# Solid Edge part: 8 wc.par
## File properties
Author: Henri
Template: Normal.par
Last saved by: Henri
Revision: 2
Application: Solid Edge
Accuracy: 0,990
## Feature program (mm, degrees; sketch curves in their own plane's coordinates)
sketch for "unnamed Protrusion 1" plane through (0, 0, 0) normal (0, 0, 1) x-axis (1, 0, 0)
  line (35, -25) -> (-35, -25)
  line (-35, -25) -> (-35, 25)
  line (-35, 25) -> (35, 25)
  line (35, 25) -> (35, -25)
extrude "unnamed Protrusion 1" add finite 2.5 along +normal
sketch for "ExtrudedProtrusion_3" plane through (0, 0, 2.5) normal (0, 0, 1) x-axis (0, 1, 0)
  line (7, 25) -> (7.9468, 13.7663)
  line (7, 30) -> (7, 25)
  line (7, 30) -> (-7, 30)
  line (-7, 30) -> (-7, 25)
  line (-7, 25) -> (-7.9468, 13.7663)
extrude "ExtrudedProtrusion_3" add finite 2.5 along +normal
lofted protrusion "unnamed LoftedProtrusion 1"
lofted protrusion "unnamed LoftedProtrusion 2"
lofted cutout "unnamed LoftedCutout 1"
lofted protrusion "unnamed LoftedProtrusion 3"
lofted cutout "unnamed LoftedCutout 2"
swept cutout "unnamed SweptCutout 1"
fillet "Round_8" radius 0.5
fillet "Round_9" radius 0.5
fillet "Round_11" radius 1
fillet "Round_12" radius 2
sketch for "ExtrudedProtrusion_8" plane through (0, 0, 37.5) normal (0, 0, 1) x-axis (0, 1, 0)
  line (8.5, 25) -> (-8.5, 25)
  line (-8.5, 31.5) -> (-8.5, 25)
  line (8.5, 31.5) -> (-8.5, 31.5)
  line (8.5, 31.5) -> (8.5, 25)
extrude "ExtrudedProtrusion_8" add finite 1 along -normal
fillet "unnamed Round 1"
sketch for "ExtrudedProtrusion_9" plane through (-28.25, 0, 37.5) normal (0, 0, 1) x-axis (0, 1, 0)
  circle centre (0, -0.4854) radius 0.5
extrude "ExtrudedProtrusion_9" add finite 1 along +normal
chamfer "Chamfer_1" setback 0.25
fillet "Round_15" radius 0.25
lofted protrusion "unnamed LoftedProtrusion 4"
lofted cutout "unnamed LoftedCutout 3"
lofted cutout "unnamed LoftedCutout 4"
fillet "Round_16" radius 1.5
swept protrusion "unnamed SweptProtrusion 1"
fillet "Round_17" radius 0.25
sketch for "ExtrudedCutout_3" #1 plane through (0, 0, 30) normal (0, 0, 1) x-axis (0, 1, 0)
  circle centre (17.0293, -17.5) radius 6.3132
sketch for "ExtrudedCutout_3" #2 plane through (0, 0, 30) normal (0, 0, 1) x-axis (0, 1, 0)
  circle centre (17.0293, -17.5) radius 5.8132
extrude "ExtrudedCutout_3" cut finite 2 along +normal
fillet "Round_18" radius 1
lofted cutout "unnamed LoftedCutout 5"
swept cutout "unnamed SweptCutout 2"
lofted cutout "unnamed LoftedCutout 6"
fillet "Round_19" radius 1.5
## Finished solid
Body 1: solid body, 126 faces, 254 edges, 135 vertices.
  Faces by surface: cylinder 44, plane 42, blend 14, torus 11, spline 9, sphere 4, cone 1, swept 1
  Edges by curve: line 120, circle 64, ellipse 40, intersection 25, curve on surface 5
Bounding box of the edges (mm; curved faces can reach further): 70.000 x 50.000 x 40.716, from (-35, -25, 0) to (35, 25, 40.7161).
Cylindrical faces by radius (mm): R0.25 x4, R0.5 x19, R1 x14, R1.5 x5, R5.8132 x2
Conical faces (half-angle, radius in mm at the cone's reference point): 45 deg R0.5 x1
Toroidal faces (ring radius, tube radius in mm): R0.25 r0.25 x1, R1 r1 x1, R1.285 r0.25 x1, R1.5 r1 x2, R2.5 r1 x2, R2.5046 r0.25 x1, R4.3132 r1.5 x1, R5.5313 r0.25 x1, R6.0632 r0.25 x1
Spherical faces by radius (mm): R0.5 x4
Planar faces by outward normal: +x 4, +y 3, +z 10, -x 4, -y 4, -z 3, oblique 14
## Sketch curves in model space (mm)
circle centre (17.5, 18.5, 0) radius 0.75
circle centre (17.5, 20.5, 0) radius 0.25
line (17.5, 18.5, 0) -> (14.4745, 18.5, 0)
circle centre (17.5, 17.0293, 30) radius 5.8132
circle centre (17.5, 17.0293, 30) radius 6.3132
circle centre (17.5, 20.5, 2.5) radius 0.25
line (15.4818, 20.5, 2.5) -> (19.9001, 20.5, 2.5)
line (17.5, 20.5, 2.5) -> (17.5, 20.5, 9.3127)
line (17.5, 20.5, 9.3127) -> (17.5, 21.8425, 35.9531)
line (17.5, 21.8425, 35.9531) -> (17.5, 21.8425, 37.8065)
arc centre (17.5, 18.5077, 39.1211) radius 1.285 from (17.5, 17.3853, 39.7466) through (17.5, 17.847, 40.2232) to (17.5, 18.485, 40.4059)
arc centre (17.5, 18.5829, 34.8754) radius 5.5313 from (17.5, 19.9627, 40.2319) through (17.5, 19.2297, 40.3688) to (17.5, 18.485, 40.4059)
arc centre (17.5, 19.3379, 37.8065) radius 2.5046 from (17.5, 19.9627, 40.2319) through (17.5, 21.3175, 39.3408) to (17.5, 21.8425, 37.8065)
line (17.5, 21.8425, 35.9531) -> (17.5, 21.8425, 37.8065)
line (17.5, 17.3853, 39.7466) -> (17.5, 17.3844, 39.745)
arc centre (17.5, 18.5077, 39.1211) radius 1.285 from (17.5, 17.3853, 39.7466) through (17.5, 17.847, 40.2232) to (17.5, 18.485, 40.4059)
arc centre (17.5, 18.5829, 34.8754) radius 5.5313 from (17.5, 19.9627, 40.2319) through (17.5, 19.2297, 40.3688) to (17.5, 18.485, 40.4059)
arc centre (17.5, 19.3379, 37.8065) radius 2.5046 from (17.5, 19.9627, 40.2319) through (17.5, 21.3175, 39.3408) to (17.5, 21.8425, 37.8065)
arc centre (18.8902, 21.7938, 37.5) radius 0.35 from (18.8902, 21.4438, 37.5) through (19.2367, 21.7443, 37.5) to (18.9883, 22.1298, 37.5)
arc centre (17.5, 17.0293, 37.5) radius 5.3132 from (16.0117, 22.1298, 37.5) through (17.5, 22.3425, 37.5) to (18.9883, 22.1298, 37.5)
arc centre (16.1098, 21.7938, 37.5) radius 0.35 from (16.0117, 22.1298, 37.5) through (15.7633, 21.7443, 37.5) to (16.1098, 21.4438, 37.5)
line (16.1098, 21.4438, 37.5) -> (18.8902, 21.4438, 37.5)
circle centre (17.5, 16.6527, 32.5) radius 0.625
circle centre (17.5, 17.0293, 32.5) radius 6.3132
arc centre (17.5, 17.0293, 32.5) radius 5.8132 from (21.7977, 20.9438, 32.5) through (16.9776, 11.2396, 32.5) to (13.2023, 20.9438, 32.5)
line (13.2023, 20.9438, 32.5) -> (21.7977, 20.9438, 32.5)
circle centre (17.5, 17.0293, 37.5) radius 6.3132
arc centre (17.5, 17.0293, 37.5) radius 5.8132 from (21.7977, 20.9438, 37.5) through (16.9776, 11.2396, 37.5) to (13.2023, 20.9438, 37.5)
line (13.2023, 20.9438, 37.5) -> (21.7977, 20.9438, 37.5)
circle centre (17.5, 18.7362, 2.5) radius 0.75
circle centre (17.5, 19.5787, 2.5) radius 2.5
circle centre (17.5, 17.0293, 2.5) radius 5.8132
circle centre (17.5, 17.0293, 2.5) radius 6.3132
line (17.5, 26.1988, 2.5) -> (17.5, 6.7907, 2.5)
line (25, 27.1495, 2.5) -> (25, -5.2769, 2.5)
line (10, 27.1495, 2.5) -> (10, -5.2769, 2.5)
line (8.2451, 23.4438, 2.5) -> (28.5989, 23.4438, 2.5)
line (29.2157, 10.4503, 2.5) -> (5.8191, 10.4503, 2.5)
line (8.2451, 20.9438, 2.5) -> (27.9044, 20.9438, 2.5)
circle centre (-27.7646, 0, 37.5) radius 0.5
circle centre (-27.6671, 0, -1.178) radius 1
line (-27.6671, 0, 7.1613) -> (-27.6671, 0, -1.178)
arc centre (-26.6671, 0, 7.1613) radius 1 from (-26.9642, 0, 8.1161) through (-27.4724, 0, 7.7541) to (-27.6671, 0, 7.1613)
line (-27.6671, 0, 24.9234) -> (-27.6671, 0, 21.3457)
arc centre (-25.1671, 0, 21.3457) radius 2.5 from (-27.6671, 0, 21.3457) through (-27.0949, 0, 19.7539) to (-25.6402, 0, 18.8908)
line (-25.6402, 0, 18.8908) -> (-19.6932, 0, 17.7448)
arc centre (-20.1663, 0, 15.29) radius 2.5 from (-19.6932, 0, 17.7448) through (-18.6109, 0, 17.2473) to (-17.8818, 0, 16.3053)
line (-17.8818, 0, 16.3053) -> (-17.4695, 0, 15.3778)
arc centre (-19.7541, 0, 14.3625) radius 2.5 from (-17.4695, 0, 15.3778) through (-17.2572, 0, 14.2371) to (-17.5828, 0, 13.1233)
line (-17.5828, 0, 13.1233) -> (-18.5438, 0, 11.4393)
arc centre (-20.7151, 0, 12.6785) radius 2.5 from (-18.5438, 0, 11.4393) through (-19.1492, 0, 10.7297) to (-19.9725, 0, 10.2913)
line (-19.9725, 0, 10.2913) -> (-26.9642, 0, 8.1161)
line (-31.5, -8.5, 37.5) -> (-25, -8.5, 37.5)
line (-25, 8.5, 37.5) -> (-25, -8.5, 37.5)
line (-31.5, 8.5, 37.5) -> (-25, 8.5, 37.5)
line (-31.5, 8.5, 37.5) -> (-31.5, -8.5, 37.5)
line (-31, -8, 37.5) -> (-25.5, -8, 37.5)
line (-25.5, -8, 37.5) -> (-25.5, 8, 37.5)
line (-25.5, 8, 37.5) -> (-31, 8, 37.5)
line (-31, 8, 37.5) -> (-31, -8, 37.5)
closed spline through (-21.5, 0, 102.5), (-12.1327, -5.9951, 102.5), (-3.5008, 0, 102.5), (-12.1327, 5.9951, 102.5)
ellipse centre (-12.5, 0, 102.5) radii 11, 8
line (-25, 7, 102.5) -> (-25, -7, 102.5)
line (-25, 7, 102.5) -> (-13.7663, 7.9468, 102.5)
line (-25, -7, 102.5) -> (-13.7663, -7.9468, 102.5)
line (-30, -7, 102.5) -> (-25, -7, 102.5)
line (-30, 7, 102.5) -> (-25, 7, 102.5)
line (-30, 7, 102.5) -> (-30, -7, 102.5)
ellipse centre (-16.2132, 0, 12.5) radii 3.5816, 2.2573
spline (-13.6601, -5.9487, 12.5) -> (-3.5008, 0, 12.5) -> (-13.6601, 5.9487, 12.5)
line (-30, -7, 12.5) -> (-25, -7, 12.5)
line (-25, -4.9929, 12.5) -> (-25, -7, 12.5)
line (-13.5983, -5.9539, 12.5) -> (-25, -4.9929, 12.5)
spline (-13.5983, 5.9539, 12.5) -> (-3.505, -0.1793, 12.5) -> (-13.5983, -5.9539, 12.5)
line (-25, 4.9929, 12.5) -> (-13.5983, 5.9539, 12.5)
line (-25, 7, 12.5) -> (-25, 4.9929, 12.5)
line (-30, 7, 12.5) -> (-25, 7, 12.5)
line (-30, 7, 12.5) -> (-30, -7, 12.5)
closed spline through (-21.5, 0, 22.5), (-12.1327, -5.9951, 22.5), (-3.5008, 0, 22.5), (-12.1327, 5.9951, 22.5)
line (-25, 7, 22.5) -> (-25, -7, 22.5)
line (-30, -7, 22.5) -> (-25, -7, 22.5)
line (-30, 7, 22.5) -> (-25, 7, 22.5)
line (-30, 7, 22.5) -> (-30, -7, 22.5)
line (-25, -7, 22.5) -> (-13.7663, -7.9468, 22.5)
ellipse centre (-12.5, 0, 22.5) radii 11, 8 from (-13.7663, -7.9468, 22.5) through (-1.5, 0, 22.5) to (-13.7663, 7.9468, 22.5)
line (-25, 7, 22.5) -> (-13.7663, 7.9468, 22.5)
line (-29.5, 6.5, 22.5) -> (-29.5, -6.5, 22.5)
line (-29.5, -6.5, 22.5) -> (-25.5, -6.5, 22.5)
line (-25.5, 6.5, 22.5) -> (-25.5, -6.5, 22.5)
line (-25.5, 6.5, 22.5) -> (-29.5, 6.5, 22.5)
line (-30, -7, 2.5) -> (-25, -7, 2.5)
line (-25, -7, 2.5) -> (-13.7663, -7.9468, 2.5)
ellipse centre (-12.5, 0, 2.5) radii 11, 8 from (-13.7663, -7.9468, 2.5) through (-1.5, 0, 2.5) to (-13.7663, 7.9468, 2.5)
line (-25, 7, 2.5) -> (-13.7663, 7.9468, 2.5)
line (-30, 7, 2.5) -> (-25, 7, 2.5)
line (-30, 7, 2.5) -> (-30, -7, 2.5)
line (35, 25, 0) -> (35, -25, 0)
line (35, -25, 0) -> (-35, -25, 0)
line (-35, -25, 0) -> (-35, 25, 0)
line (-35, 25, 0) -> (35, 25, 0)
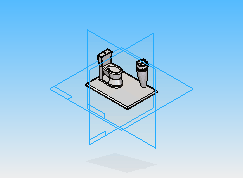
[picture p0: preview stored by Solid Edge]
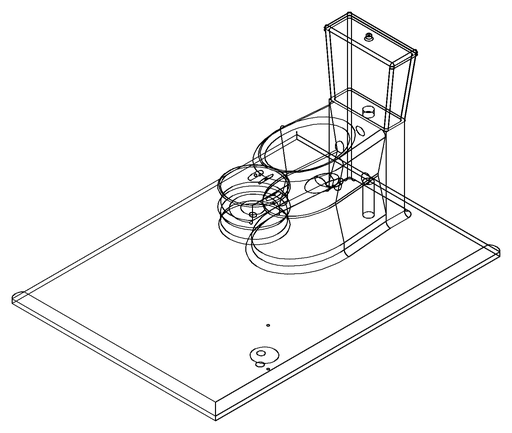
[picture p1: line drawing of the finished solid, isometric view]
